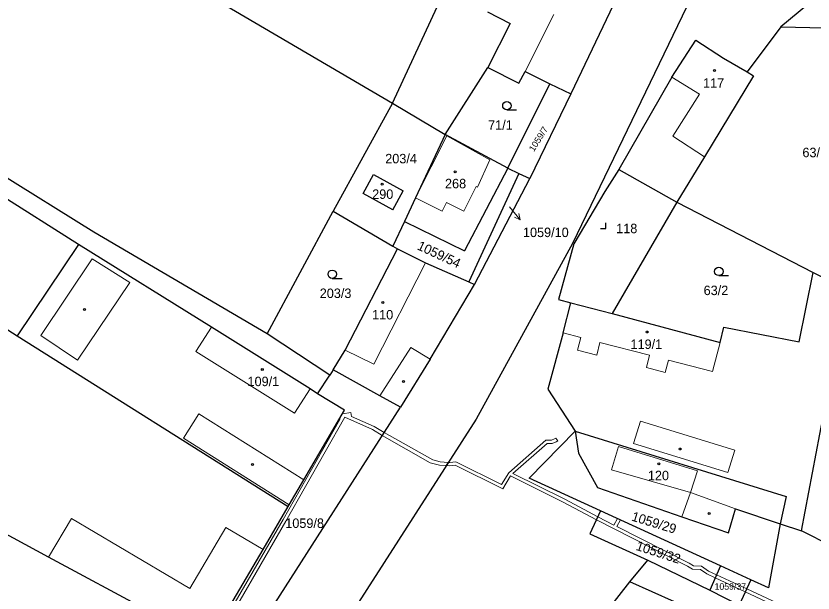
# Model space of a CAD drawing. Extents: x -694609 to -690140, y -1033292 to -1029794.
# Drawn here: x -692957.6 to -692814.5, y -1031189.2 to -1031085.6 of the extents above; entities that cross this region are included whole.
import ezdxf
from ezdxf.enums import TextEntityAlignment as Align

# ---------------------------------------------------------------- set-up
doc = ezdxf.new("R2010")
doc.units = 0
doc.header["$LTSCALE"] = 0.68
for name, color, linetype, lineweight in [('1', 7, 'Continuous', 25), ('13', 7, 'Continuous', 13), ('3', 7, 'Continuous', 25), ('4', 7, 'Continuous', 13), ('5', 7, 'Continuous', 25), ('7', 7, 'Continuous', 13)]:
    doc.layers.add(name, color=color, linetype=linetype, lineweight=lineweight)
doc.layers.add('2', color=7, linetype='Continuous')

msp = doc.modelspace()

# ---------------------------------------------------------------- linework, layer by layer
at = {"layer": '1'}
for p, q in [((-692846.75, -1031075.99), (-692858.01, -1031099.53)), ((-692833.67, -1031076.6), (-692857.71, -1031126.43)), ((-692930.66, -1031077.38), (-692890, -1031101.24)), ((-692890, -1031101.24), (-692879.49, -1031078.45)), ((-692815.42, -1031083.48), (-692820.24, -1031087.51)), ((-692872.93, -1031084.81), (-692868.88, -1031086.89)), ((-692943.64, -1031124.36), (-693005.7, -1031085.79)), ((-692868.88, -1031086.89), (-692872.88, -1031094.82)), ((-692820.24, -1031087.51), (-692826.33, -1031095.61)), ((-692839.86, -1031096.55), (-692835.56, -1031089.9)), ((-692835.56, -1031089.9), (-692830.56, -1031093.11)), ((-692830.56, -1031093.11), (-692826.33, -1031095.61)), ((-692880.55, -1031106.83), (-692872.88, -1031094.82)), ((-692872.88, -1031094.82), (-692867.3, -1031097.65)), ((-692867.3, -1031097.65), (-692866.21, -1031095.51)), ((-692866.21, -1031095.51), (-692861.73, -1031097.73)), ((-692839.86, -1031096.55), (-692849.37, -1031113.15)), ((-692825.16, -1031096.28), (-692833.98, -1031110.83)), ((-692826.33, -1031095.61), (-692825.16, -1031096.28)), ((-692869.31, -1031112.89), (-692861.73, -1031097.73)), ((-692861.73, -1031097.73), (-692858.01, -1031099.53)), ((-692858.01, -1031099.53), (-692865.37, -1031114.73)), ((-692890, -1031101.24), (-692900.68, -1031120.62)), ((-692890, -1031101.24), (-692880.55, -1031106.83)), ((-692946.41, -1031126.6), (-692981.03, -1031104.69)), ((-692880.55, -1031106.83), (-692885.88, -1031118.22)), ((-692869.31, -1031112.89), (-692880.55, -1031106.83)), ((-692833.98, -1031110.83), (-692838.95, -1031119.02)), ((-692869.31, -1031112.89), (-692877.08, -1031127.72)), ((-692867.3, -1031113.83), (-692876.32, -1031133.32)), ((-692869.31, -1031112.89), (-692867.3, -1031113.83)), ((-692867.3, -1031113.83), (-692865.37, -1031114.73)), ((-692849.37, -1031113.15), (-692851.85, -1031117.1)), ((-692849.37, -1031113.15), (-692838.95, -1031119.02)), ((-692875.29, -1031133.78), (-692865.37, -1031114.73)), ((-692889.96, -1031120.35), (-692895.28, -1031117.44)), ((-692889.96, -1031120.35), (-692888.09, -1031116.93)), ((-692885.88, -1031118.22), (-692887.85, -1031122.44)), ((-692851.85, -1031117.1), (-692857.47, -1031126.49)), ((-692838.95, -1031119.02), (-692850.53, -1031138.97)), ((-692838.95, -1031119.02), (-692814.49, -1031131.6)), ((-692912.53, -1031142.61), (-692900.68, -1031120.62)), ((-692900.68, -1031120.62), (-692889.94, -1031126.9)), ((-692887.85, -1031122.44), (-692877.08, -1031127.72)), ((-692912.53, -1031142.61), (-692943.64, -1031124.36)), ((-692946.41, -1031126.6), (-692957.43, -1031142.98)), ((-692922.53, -1031141.46), (-692946.41, -1031126.6)), ((-692857.71, -1031126.43), (-692875.01, -1031157.97)), ((-692857.47, -1031126.49), (-692860.17, -1031136.49)), ((-692898.5, -1031145.6), (-692889.09, -1031127.39)), ((-692889.09, -1031127.39), (-692884.07, -1031129.91)), ((-692884.07, -1031129.91), (-692876.32, -1031133.32)), ((-692816.95, -1031144.05), (-692814.49, -1031131.6)), ((-692814.49, -1031131.6), (-692801.98, -1031137.94)), ((-692883.24, -1031147.2), (-692875.29, -1031133.78)), ((-692876.32, -1031133.32), (-692875.29, -1031133.78)), ((-692860.17, -1031136.49), (-692857.99, -1031137.05)), ((-692859.38, -1031142.47), (-692857.99, -1031137.05)), ((-692857.99, -1031137.05), (-692850.53, -1031138.97)), ((-692850.53, -1031138.97), (-692831.18, -1031144.22)), ((-692961.81, -1031140.22), (-692957.43, -1031142.98)), ((-692904.8, -1031152.52), (-692922.53, -1031141.46)), ((-692859.38, -1031142.47), (-692862.12, -1031152.58)), ((-692831.18, -1031144.22), (-692830.51, -1031141.43)), ((-692830.51, -1031141.43), (-692816.95, -1031144.05)), ((-692957.43, -1031142.98), (-692908.74, -1031173.67)), ((-692901.29, -1031150.08), (-692912.53, -1031142.61)), ((-692900.68, -1031149.13), (-692898.5, -1031145.6)), ((-692883.24, -1031147.2), (-692888.6, -1031155.82)), ((-692900.68, -1031149.13), (-692901.29, -1031150.08)), ((-692892.26, -1031153.8), (-692900.68, -1031149.13)), ((-692903.48, -1031153.43), (-692901.29, -1031150.08)), ((-692903.48, -1031153.43), (-692904.8, -1031152.52)), ((-692862.12, -1031152.58), (-692857.23, -1031160.12)), ((-692898.6, -1031156.35), (-692903.48, -1031153.43)), ((-692888.6, -1031155.82), (-692892.26, -1031153.8)), ((-692942.13, -1031239.46), (-692888.6, -1031155.82)), ((-692905.93, -1031168.87), (-692898.6, -1031156.35)), ((-692875.01, -1031157.97), (-692911.18, -1031214.36)), ((-692816.55, -1031178.04), (-692812.59, -1031157.2)), ((-692857.23, -1031160.12), (-692865.46, -1031168.54)), ((-692857.23, -1031160.12), (-692856.63, -1031164.06)), ((-692857.23, -1031160.12), (-692819.29, -1031171.84)), ((-692856.63, -1031164.06), (-692853.2, -1031170.24)), ((-692908.54, -1031173.33), (-692905.93, -1031168.87)), ((-692852.63, -1031174.42), (-692865.46, -1031168.54)), ((-692853.2, -1031170.24), (-692838.02, -1031175.5)), ((-692819.29, -1031171.84), (-692820.41, -1031176.76)), ((-692913.26, -1031181.38), (-692908.74, -1031173.67)), ((-692908.74, -1031173.67), (-692908.54, -1031173.33)), ((-692829.67, -1031178.39), (-692828.38, -1031174.06)), ((-692828.38, -1031174.06), (-692820.41, -1031176.76)), ((-692852.63, -1031174.42), (-692854.58, -1031178.54)), ((-692831.1, -1031184.29), (-692852.63, -1031174.42)), ((-692838.02, -1031175.5), (-692829.67, -1031178.39)), ((-692820.41, -1031176.76), (-692822.48, -1031188.23)), ((-692820.41, -1031176.76), (-692816.55, -1031178.04)), ((-692951.79, -1031182.73), (-692960.18, -1031178.18)), ((-692808.06, -1031182.27), (-692816.55, -1031178.04)), ((-692854.58, -1031178.54), (-692844.13, -1031183.26)), ((-692923.09, -1031198.13), (-692913.26, -1031181.38)), ((-692923.09, -1031198.13), (-692951.79, -1031182.73)), ((-692847.36, -1031187.15), (-692844.13, -1031183.26)), ((-692844.13, -1031183.26), (-692833.01, -1031188.65)), ((-692831.1, -1031184.29), (-692833.01, -1031188.65)), ((-692825.64, -1031186.79), (-692831.1, -1031184.29)), ((-692825.64, -1031186.79), (-692827.78, -1031191.36)), ((-692822.48, -1031188.23), (-692825.64, -1031186.79)), ((-692851.21, -1031192.06), (-692847.36, -1031187.15)), ((-692819.01, -1031199.83), (-692847.36, -1031187.15)), ((-692833.01, -1031188.65), (-692827.78, -1031191.36))]:
    msp.add_line(p, q, dxfattribs=at)
for points in [[(-692820.24, -1031087.51), (-692794.09, -1031088.08), (-692801.98, -1031137.94)], [(-692895.28, -1031117.44), (-692893.41, -1031114.02), (-692888.09, -1031116.93)], [(-692887.85, -1031122.44), (-692889.94, -1031126.9), (-692889.09, -1031127.39)]]:
    msp.add_lwpolyline(points, dxfattribs=at)
at = {"layer": '13'}
for points in [[(-692922.03, -1031198.55), (-692909.15, -1031176.29), (-692898.55, -1031157.63), (-692893.61, -1031159.83), (-692891.85, -1031160.9), (-692891.49, -1031160.34), (-692893.33, -1031159.29), (-692897.4, -1031157.48), (-692897.52, -1031156.75), (-692898.97, -1031156.98), (-692899.54, -1031157.95), (-692899.44, -1031158.01), (-692909.67, -1031175.99), (-692922.55, -1031198.25)], [(-692860.94, -1031161.51), (-692861.46, -1031161.75), (-692862.48, -1031161.75), (-692869.14, -1031167.58), (-692870.42, -1031169.71), (-692878.66, -1031165.63), (-692879.72, -1031165.75), (-692879.99, -1031165.73), (-692880.36, -1031166.31), (-692879.7, -1031166.35), (-692878.76, -1031166.25), (-692870.2, -1031170.49), (-692868.8, -1031168.16), (-692859.34, -1031172.85), (-692853.38, -1031176.01), (-692837.03, -1031184.33), (-692836.12, -1031184.92), (-692834.72, -1031184.96), (-692833.53, -1031185.75), (-692832.05, -1031186.45), (-692826.66, -1031188.96), (-692818.35, -1031192.85)], [(-692804.91, -1031204.72), (-692816.26, -1031198.2), (-692819.07, -1031195.91), (-692817.53, -1031192.57), (-692826.4, -1031188.42), (-692831.8, -1031185.9), (-692833.23, -1031185.23), (-692834.54, -1031184.36), (-692835.94, -1031184.32), (-692836.73, -1031183.81), (-692849.73, -1031177.26), (-692849.08, -1031176.05), (-692849.63, -1031175.8), (-692850.27, -1031176.99), (-692853.12, -1031175.47), (-692859.06, -1031172.31), (-692868.37, -1031167.7), (-692862.26, -1031162.35), (-692861.34, -1031162.35), (-692860.59, -1031162.02), (-692860.34, -1031161.85), (-692860.69, -1031161.35), (-692860.94, -1031161.51)]]:
    msp.add_lwpolyline(points, dxfattribs=at)
msp.add_lwpolyline([(-692891.49, -1031160.34), (-692891.85, -1031160.9), (-692883.22, -1031165.79), (-692881.56, -1031166.23), (-692880.36, -1031166.31), (-692879.99, -1031165.73), (-692881.46, -1031165.63), (-692882.76, -1031165.29)], close=True, dxfattribs=at)
at = {"layer": '3'}
for p, q in [((-692869.473, -1031102.42), (-692867.723, -1031102.42)), ((-692831.403, -1031132.18), (-692829.653, -1031132.18)), ((-692900.823, -1031132.69), (-692899.073, -1031132.69))]:
    msp.add_line(p, q, dxfattribs=at)
msp.add_lwpolyline([(-692852.671, -1031123.73), (-692851.67, -1031123.73), (-692851.67, -1031122.73)], dxfattribs=at)
for centre in [(-692869.4729, -1031101.6698), (-692831.4029, -1031131.4298), (-692900.8229, -1031131.9398)]:
    msp.add_circle(centre, 0.75, dxfattribs=at)
at = {"layer": '4'}
for p, q in [((-692866.21, -1031095.51), (-692861.03, -1031085.32)), ((-692834.89, -1031099.63), (-692839.86, -1031096.55)), ((-692885.88, -1031118.22), (-692880.26, -1031107.1)), ((-692872.51, -1031111.4), (-692880.26, -1031107.1)), ((-692872.51, -1031111.4), (-692874.74, -1031116.32)), ((-692874.97, -1031116.21), (-692877.18, -1031120.64)), ((-692874.74, -1031116.32), (-692874.97, -1031116.21)), ((-692881.1, -1031120.63), (-692885.88, -1031118.22)), ((-692880.31, -1031119.05), (-692881.1, -1031120.63)), ((-692877.18, -1031120.64), (-692880.31, -1031119.05)), ((-692943.92, -1031129.2), (-692953.15, -1031142.92)), ((-692937.18, -1031133.4), (-692943.92, -1031129.2)), ((-692893.38, -1031148.1), (-692884.07, -1031129.91)), ((-692937.18, -1031133.4), (-692946.56, -1031147.35)), ((-692922.53, -1031141.46), (-692925.3, -1031145.82)), ((-692856.18, -1031143.3), (-692859.38, -1031142.47)), ((-692946.56, -1031147.35), (-692953.15, -1031142.92)), ((-692856.77, -1031145.57), (-692856.18, -1031143.3)), ((-692852.75, -1031144.18), (-692853.33, -1031146.46)), ((-692843.84, -1031146.48), (-692852.75, -1031144.18)), ((-692831.18, -1031144.22), (-692832.51, -1031149.4)), ((-692925.3, -1031145.82), (-692907.63, -1031156.87)), ((-692898.5, -1031145.6), (-692893.38, -1031148.1)), ((-692853.33, -1031146.46), (-692856.77, -1031145.57)), ((-692844.41, -1031148.7), (-692843.84, -1031146.48)), ((-692840.45, -1031147.35), (-692841.02, -1031149.58)), ((-692832.51, -1031149.4), (-692840.45, -1031147.35)), ((-692841.02, -1031149.58), (-692844.41, -1031148.7)), ((-692904.8, -1031152.52), (-692907.63, -1031156.87)), ((-692927.52, -1031161.36), (-692924.77, -1031156.99)), ((-692924.77, -1031156.99), (-692905.93, -1031168.87)), ((-692845.47, -1031158.31), (-692846.7, -1031162.32)), ((-692828.55, -1031163.53), (-692845.47, -1031158.31)), ((-692927.52, -1031161.36), (-692908.54, -1031173.33)), ((-692846.7, -1031162.32), (-692829.79, -1031167.55)), ((-692849.45, -1031162.84), (-692850.65, -1031167.05)), ((-692849.45, -1031162.84), (-692835.22, -1031167.24)), ((-692829.79, -1031167.55), (-692828.55, -1031163.53)), ((-692850.65, -1031167.05), (-692836.52, -1031171.14)), ((-692836.52, -1031171.14), (-692835.22, -1031167.24)), ((-692836.52, -1031171.14), (-692838.02, -1031175.5)), ((-692836.52, -1031171.14), (-692828.38, -1031174.06)), ((-692951.79, -1031182.73), (-692947.68, -1031175.78)), ((-692947.68, -1031175.78), (-692926.4, -1031188.37)), ((-692926.4, -1031188.37), (-692919.93, -1031177.43)), ((-692913.26, -1031181.38), (-692919.93, -1031177.43))]:
    msp.add_line(p, q, dxfattribs=at)
for points in [[(-692833.98, -1031110.83), (-692839.67, -1031107.15), (-692834.89, -1031099.63)], [(-692892.26, -1031153.8), (-692886.7, -1031145.07), (-692883.24, -1031147.2)]]:
    msp.add_lwpolyline(points, dxfattribs=at)
at = {"layer": '5'}
for centre in [(-692832.1668, -1031095.3292), (-692878.7368, -1031113.5492), (-692891.8468, -1031115.7592), (-692891.7368, -1031136.9892), (-692945.3368, -1031138.2692), (-692844.2868, -1031142.3092), (-692913.3868, -1031149.0592), (-692888.0268, -1031151.1892), (-692838.3368, -1031163.3192), (-692915.1268, -1031166.0992), (-692842.1968, -1031165.9692), (-692833.1568, -1031174.8992)]:
    msp.add_circle(centre, 0.175, dxfattribs=at)
at = {"layer": '7'}
msp.add_line((-692867.081, -1031122.139), (-692867.341, -1031121.05), dxfattribs=at)
msp.add_lwpolyline([(-692869.01, -1031119.84), (-692867.081, -1031122.139), (-692868.108, -1031121.694)], dxfattribs=at)

# ---------------------------------------------------------------- texts
at = {"layer": '2'}
for s, height, p in [('117', 1.7, (-692832.339, -1031098.445)), ('71/1', 1.7, (-692870.629, -1031105.995)), ('63/1', 1.7, (-692814.179, -1031110.925)), ('203/4', 1.7, (-692888.47, -1031112.025)), ('268', 1.7, (-692878.679, -1031116.505)), ('290', 1.7, (-692891.759, -1031118.405)), ('118', 1.7, (-692847.939, -1031124.565)), ('63/2', 1.7, (-692831.919, -1031135.685)), ('203/3', 1.7, (-692900.23, -1031136.205)), ('110', 1.7, (-692891.779, -1031140.055)), ('119/1', 1.7, (-692844.42, -1031145.355)), ('109/1', 1.7, (-692913.2, -1031152.035)), ('120', 1.7, (-692842.249, -1031168.925)), ('1059/8', 1.7, (-692905.79, -1031177.495)), ('1059/37', 1.172, (-692829.34, -1031188.593))]:
    msp.add_text(s, height=height, dxfattribs=at).set_placement(p, align=Align.CENTER)
at = {"layer": '2', "width": 1.05}
msp.add_text('1059/7', height=1.14, rotation=58, dxfattribs=at).set_placement((-692863.3222, -1031107.9471), align=Align.CENTER)
at = {"layer": '2'}
msp.add_text('1059/10', height=1.7, dxfattribs=at).set_placement((-692866.58, -1031125.265))
for s, rotation, p in [('1059/54', 335, (-692881.9967, -1031129.1494)), ('1059/29', 343, (-692843.2765, -1031177.3445)), ('1059/32', 342, (-692842.5167, -1031182.6775))]:
    msp.add_text(s, height=1.7, rotation=rotation, dxfattribs=at).set_placement(p, align=Align.CENTER)

doc.saveas('drawing.dxf')
